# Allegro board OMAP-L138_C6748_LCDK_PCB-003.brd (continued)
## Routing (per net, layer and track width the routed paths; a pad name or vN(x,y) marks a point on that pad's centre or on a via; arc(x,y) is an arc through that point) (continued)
N26585231: length 2.2
  TOP w0.121: v1(11.94,71.63) 12.13,71.82 Q4.1
  BOTTOM w0.121: R28.2 12.19,71.37 v1(11.94,71.63)
N27037804: length 3.2
  TOP w0.121: U9.7 58.4,63.09 58.75,62.74 v1(59.69,62.74)
  BOTTOM w0.121: v1(59.69,62.74) R42.1
N27170750: length 4.6
  TOP w0.121: U3.11 25.9,71.87 25.4,71.37 R19.2 R20.2
N27170752: length 4.4
  TOP w0.121: R18.1 R17.2 24.66,72.37 U3.10
N27473148: length 4.2
  TOP w0.121: v1(22.86,5.84) 22.86,4.12 J11.3
  BOTTOM w0.121: R150.2 C173.2 v1(22.86,5.84)
N27493630: length 14.1
  TOP w0.254: v1(85.09,10.16) 85.02,10.23 U8.16 ; U8.1 80.01,14.52 v1(80.01,15.24)
  LYR3 w0.457: v1(85.09,10.16) v1(80.01,10.16)
  LYR4 w0.457: v1(80.01,15.24) v1(80.01,10.16)
  BOTTOM w0.457: v1(85.09,10.16) C21.1 ; v1(80.01,15.24) C20.1 ; R30.1 v1(80.01,10.16)
N27494415: length 9.3
  TOP w0.254: U8.19 v1(86.09,11.95)
  BOTTOM w0.457: C22.1 FB2.1 87.12,10.92 v1(86.09,11.95) 85.85,12.19 C23.1
N27494781: length 6.8
  TOP w0.457: J3.1 v1(84.13,8.38)
  BOTTOM w0.457: v1(84.13,8.38) 84.84,8.38 85.09,8.13 C24.1 85.6,7.37 85.85,7.11 85.85,6.1 86.04,5.91 FB2.2
N27611173: length 2.8
  TOP w0.121: v1(65.71,19.56) J16.28
  BOTTOM w0.121: R199.1 65.28,19.13 v1(65.71,19.56)
N27611176: length 2.7
  TOP w0.121: J16.27 v1(65.21,13.46)
  BOTTOM w0.121: v1(65.21,13.46) 65.21,14.41 R198.1
N27655467: length 2.8
  TOP w0.121: v1(15.49,8.62) U26.D1
  BOTTOM w0.121: C211.2 16.51,9.65 15.49,8.64 v1(15.49,8.62)
N27655536: length 4.6
  TOP w0.121: U26.D2 14.22,9.14 15.24,9.14 15.49,9.4 v1(15.49,9.65)
  BOTTOM w0.121: v1(15.49,9.65) 15.49,9.91 16.51,10.92 C212.2
N27655572: length 3.6
  TOP w0.121: U26.B2 14.48,5.84 v1(15.49,5.84)
  BOTTOM w0.121: C213.2 v1(15.49,5.84)
N27655608: length 4.2
  TOP w0.121: v1(11.7,4.84) U26.A4
  BOTTOM w0.121: v1(11.7,4.84) 11.43,4.57 C214.2
N27658869: length 3.8
  TOP w0.121: v1(15.49,7.62) U26.C1
  BOTTOM w0.121: v1(15.49,7.62) 16,7.11 R207.1 R203.2
N27689876: length 1.8
  BOTTOM w0.121: J13.12 95.12,73.41 R181.2
N27790142: length 2.1
  TOP w0.121: v1(7.37,89.66) 6.36,89.66 D2.1
  BOTTOM w0.121: R1.2 7.11,89.41 v1(7.37,89.66)
N27790158: length 21.5
  TOP w0.121: U2.3 8.37,75.7 8.13,75.95 8.13,76.45 v1(8.64,76.96)
  LYR3 w0.133: v1(8.64,76.96) 11.3,79.63 11.3,83.69 7.87,87.12 v1(6.35,87.12)
  BOTTOM w0.121: R1.1 v1(6.35,87.12) 7.87,87.12 8.38,87.63 R270.2
N27799298: length 16.9
  TOP w0.254: v1(54.96,36.1) U7.U12
  LYR3 w0.133: v1(54.96,36.1) 54.36,35.5 54.36,31.75 54.61,31.5 54.61,29.32 v1(55.36,28.57)
  BOTTOM w0.121: R33.1 50.04,24.64 51.56,26.16 54.1,26.16 54.97,27.03 54.97,28.18 55.36,28.56 v1(55.36,28.57)
N27851951: length 2.1
  TOP w0.254: U8.11 v1(81.8,9.14)
  BOTTOM w0.457: v1(81.8,9.14) 81.8,10.15 R30.2
N27881562: length 49.2
  TOP w0.095: v1(60.96,57.91) 61.36,57.51 61.36,57.14 61.75,56.76 61.75,54.2 62.38,53.57 62.38,50.05 62.15,49.81 62.15,44.89 U7.J2
  TOP w0.121: C90.1 v1(46.74,83.06)
  LYR3 w0.102: v1(60.96,57.91) 60.5,58.37 60.5,59.44 58.22,61.72 55.88,61.72 52.83,64.77 52.83,71.04 50.09,73.79 50.09,82.17 48.77,83.49 47.17,83.49 v1(46.74,83.06)
N27882349: length 46.4
  TOP w0.095: U7.J1 61.87,45.41 61.87,49.93 62.1,50.16 62.1,53.45 61.47,54.09 61.47,56.64 v1(60.96,57.15)
  TOP w0.121: C91.1 v1(48.01,83.06)
  LYR3 w0.102: v1(48.01,83.06) 48.13,83.19 48.64,83.19 49.78,82.04 49.78,73.66 52.53,70.92 52.53,64.64 55.75,61.42 58.09,61.42 60.2,59.31 60.2,58.24 60.57,57.87 60.57,57.54 v1(60.96,57.15)
N27882474: length 49.1
  TOP w0.095: U7.L2 60.57,44.91 60.57,50.17 59.84,50.9 59.84,56.12 59.57,56.4 59.57,57.05 59.66,57.15 v1(59.69,57.15)
  TOP w0.121: C92.1 v1(45.21,83.06)
  LYR3 w0.102: v1(45.21,83.06) 45.33,83.06 45.38,83.01 45.59,83.01 46.48,82.12 48.18,82.12 48.97,81.33 48.97,73.2 51.51,70.66 51.51,63.37 54.36,60.53 57.58,60.53 58.8,59.31 58.8,58.37 59.3,57.87 59.3,57.54 v1(59.69,57.15)
N27882599: length 50.1
  TOP w0.095: v1(59.69,57.91) 59.29,57.51 59.29,56.28 59.56,56.01 59.56,50.79 60.29,50.06 60.29,45.43 U7.L1
  TOP w0.121: C93.1 v1(43.94,83.06)
  LYR3 w0.102: v1(43.94,83.06) 44.33,83.45 45.58,83.45 46.61,82.42 48.31,82.42 49.28,81.46 49.28,73.33 51.82,70.79 51.82,63.5 54.48,60.83 57.71,60.83 59.11,59.44 59.11,58.5 v1(59.69,57.91)
N28002926: length 2.6
  TOP w0.121: R43.1 v1(60.96,22.1)
  BOTTOM w0.121: Y3.3 60.96,23.09 v1(60.96,22.1)
N28068081: length 2.3
  TOP w0.121: v1(82.3,40.13) D6.2
  BOTTOM w0.121: R210.2 v1(82.3,40.13)
N28068095: length 1.4
  TOP w0.121: D6.1 Q5.6
N28068166: length 1.6
  TOP w0.121: v1(87.12,41.4) 86.6,41.4 D7.2
  BOTTOM w0.121: v1(87.12,41.4) R211.2
N28068180: length 2.6
  TOP w0.121: D7.1 85.85,42.66 85.6,42.41 85.6,41.4 85.36,41.16 Q5.3
N28115819: length 2.3
  TOP w0.121: D5.2 v1(80.01,40.13)
  BOTTOM w0.121: v1(80.01,40.13) R87.1
N28153433: length 8.2
  BOTTOM w0.121: S3.1 98.77,6.13 98.04,6.86 R223.1 97.28,8.12 S3.2
N28153568: length 8.5
  BOTTOM w0.121: S2.2 5.3,18.58 4.57,19.3 R222.1 3.82,20.32 S2.1
N28157154: length 3.2
  TOP w0.121: v1(50.8,62.74) SW1.16
  BOTTOM w0.121: R76.2 v1(50.8,62.74)
N28157182: length 3.2
  TOP w0.121: v1(53.34,62.74) SW1.15
  BOTTOM w0.121: R77.2 v1(53.34,62.74)
N28157237: length 3.2
  TOP w0.121: v1(55.88,62.74) SW1.14
  BOTTOM w0.121: R78.2 v1(55.88,62.74)
N28157266: length 4
  TOP w0.121: SW1.13 58.67,60.58 58.67,58.17 v1(58.42,57.91)
  BOTTOM w0.121: R79.2 v1(58.42,57.91)
N28226673: length 3.2
  TOP w0.121: v1(60.96,62.74) SW1.12
  BOTTOM w0.121: R253.2 v1(60.96,62.74)
N28226728: length 3.2
  TOP w0.121: v1(68.58,62.74) SW1.9
  BOTTOM w0.121: R256.2 v1(68.58,62.74)
N28226757: length 3.2
  TOP w0.121: v1(66.04,62.74) SW1.10
  BOTTOM w0.121: R255.2 v1(66.04,62.74)
N28226786: length 3.2
  TOP w0.121: v1(63.5,62.74) SW1.11
  BOTTOM w0.121: R254.2 v1(63.5,62.74)
N28488580: length 20
  TOP w0.457: TP20.1 17.36,4.66 16.51,3.81 8.89,3.81 8.06,4.64 8.06,7.11 ; v1(6.35,7.11) 8.06,7.11 ; 8.06,7.11 TP19.1
  BOTTOM w0.457: v1(6.35,7.11) R268.2 7.37,6.6 7.45,6.52 D8.2
N28488978: length 2.5
  TOP w0.457: U26.B5 v1(9.92,6.62)
  BOTTOM w0.457: R268.1 9.43,7.11 v1(9.92,6.62)
N28544289: length 27.7
  TOP w0.121: R269.2 78.74,24.89 77.47,23.62 v1(77.47,22.35)
  TOP w0.254: v1(60.56,32.1) U7.K17
  LYR3 w0.121: 61.21,30.1 61.21,31.88 60.99,32.1 v1(60.56,32.1)
  LYR3 w0.133: 61.21,30.1 61.21,28.7 65.79,24.13 68.58,24.13 69.85,22.86 76.96,22.86 v1(77.47,22.35)
N28544350: length 22.1
  TOP w0.121: R272.2 v1(80.01,25.4)
  TOP w0.254: v1(62.16,31.3) U7.J18
  LYR3 w0.121: v1(62.16,31.3) 62.56,30.9 62.56,30.1
  LYR3 w0.133: 62.56,30.1 62.56,30.02 64.64,27.94 70.1,27.94 71.12,26.92 78.49,26.92 v1(80.01,25.4)
N28561453: length 3.4
  TOP w0.121: v1(33.02,20.83) 32.78,21.07 U21.69
  BOTTOM w0.121: R274.2 32.32,19.88 32.64,20.19 32.64,20.45 v1(33.02,20.83)
N28567458: length 5.8
  TOP w0.121: J6.5 83.82,25.4 82.04,27.18 R64.1
N200921000: length 2.3
  TOP w0.121: v1(75.95,40.13) D4.2
  BOTTOM w0.121: R88.1 v1(75.95,40.13)
N281146221: length 1.4
  TOP w0.121: D4.1 Q6.6
N281146431: length 2.6
  TOP w0.121: D5.1 79.5,42.66 79.25,42.41 79.25,41.4 79.01,41.16 Q6.3

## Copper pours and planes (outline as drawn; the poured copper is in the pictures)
1V2_LDO on LYR3: 59.44,30.23 59.18,30.48 59.18,31.24 58.93,31.5 58.67,31.5 58.42,31.75 58.42,33.78 58.93,34.29 58.93,37.85 57.91,38.86 57.91,40.01 58.45,40.13 57.91,40.26 57.91,44.45 57.66,44.7 57.15,44.7 56.9,44.96 56.9,46.48 57.15,46.74 58.67,46.74 58.93,46.48 58.93,46.23 59.18,45.97 59.69,45.97 59.94,45.72 59.94,40.64 60.2,40.39 61.09,40.39 61.72,39.75 63.12,39.75 64.26,38.61 64.26,36.32 61.09,33.15 59.69,33.15 59.56,33.02 59.56,32.13 60.2,31.5 60.2,30.48 59.94,30.23
1V8_LDO on LYR3: 60.2,46.48 60.2,47.75 59.94,48.01 54.61,48.01 54.36,47.75 54.36,39.62 55.75,38.23 56.01,38.23 56.9,37.34 56.9,34.29 57.15,34.04 58.17,34.04 58.67,34.54 58.67,37.59 57.66,38.61 57.66,44.2 57.4,44.45 56.9,44.45 56.64,44.7 56.64,46.74 56.9,46.99 58.93,46.99 59.18,46.74 59.18,46.48 59.44,46.23 59.94,46.23
5V_IN on TOP: 10.29,76.2 11.3,76.2 11.3,77.34 11.94,77.98 13.97,77.98 14.48,78.49 14.48,80.77 13.97,81.28 11.94,81.28 10.29,79.63 10.29,76.88 9.83,76.88 9.83,76.52 10.29,76.52
GND_EARTH on LYR2_GND, LYR5_PWR: 63.75,0.51 63.75,7.37 64.26,7.87 65.28,7.87 65.79,7.37 65.79,4.32 66.55,3.56 76.2,3.56 76.96,4.32 76.96,7.37 77.47,7.87 78.49,7.87 78.99,7.37 78.99,4.32 79.76,3.56 91.69,3.56 91.69,2.29 92.46,1.52 99.31,1.52 100.08,2.29 100.08,88.9 99.31,89.66 54.61,89.66 53.85,88.9 53.85,87.38 53.34,86.87 51.56,86.87 51.05,87.38 51.05,89.15 50.29,89.92 41.66,89.92 40.89,89.15 40.89,88.14 40.39,87.63 34.29,87.63 33.78,88.14 33.78,89.41 33.02,90.17 26.67,90.17 25.91,89.41 25.91,88.14 25.4,87.63 23.37,87.63 22.86,88.14 22.86,90.93 57.91,90.93 58.42,90.42 69.34,90.42 69.85,90.93 101.09,90.93 101.09,0.51
VCC_1V3D on BOTTOM: 42.42,73.15 42.42,74.17 42.67,74.42 43.43,74.42 43.94,74.93 43.94,79.5 43.43,80.01 38.86,80.01 38.86,78.49 38.61,78.23 34.04,78.23 34.04,80.01 34.54,80.52 36.07,80.52 36.83,81.28 44.45,81.28 45.47,80.26 45.47,73.15 47.5,71.12 47.5,61.47 49.02,59.94 49.02,54.86 49.53,54.36 57.53,54.36 60.96,50.93 60.96,47.24 61.72,47.24 61.98,46.99 61.98,45.85 61.72,45.59 61.09,45.59 60.2,46.48 60.2,49.78 57.15,52.83 48.77,52.83 47.5,54.1 47.5,57.66 45.97,59.18 45.97,70.36 43.43,72.9 42.67,72.9
VCC_1V3D on LYR3: 61.21,46.74 61.72,46.74 61.98,46.48 61.98,43.18 62.23,42.93 65.28,42.93 65.53,42.67 65.53,42.29 65.28,42.04 65.15,42.04 64.14,41.02 64.14,40.01 63.88,39.75 63.63,39.75 62.74,40.64 60.45,40.64 60.2,40.89 60.2,41.15 60.71,41.66 60.71,46.23
VCC_1V3D on LYR3: 66.8,29.72 66.55,29.46 65.79,29.46 65.53,29.72 65.53,31.24 64.77,32 64.77,33.78 65.28,34.29 66.29,34.29 66.8,33.78
VCC_1V3D on LYR4: 61.72,46.74 61.98,46.48 61.98,43.18 62.23,42.93 63.75,42.93 64.01,42.67 64.01,37.85 64.26,37.59 64.26,36.83 65.53,35.56 65.53,33.53 62.23,33.53 61.98,33.78 61.98,34.29 60.2,36.07 60.2,37.34 59.69,37.85 58.93,37.85 58.67,38.1 58.67,40.89 58.93,41.15 60.45,41.15 60.71,41.4 60.71,46.48 60.96,46.74
VCC_1V8D on BOTTOM: 8.51,57.4 10.67,57.4 11.18,56.9 11.18,54.61 11.43,54.36 12.45,54.36 12.7,54.61 12.7,56.39 13.21,56.9 28.7,56.9 29.21,56.39 29.21,22.35 29.46,22.1 30.73,22.1 30.99,22.35 30.99,48.51 31.24,48.77 34.04,48.77 34.04,47.5 34.29,47.24 36.2,47.24 36.45,47.5 36.45,48.51 36.7,48.77 38.86,48.77 39.12,48.51 39.12,47.5 39.37,47.24 41.15,47.24 41.4,47.5 41.4,48.77 41.66,49.02 45.97,49.02 46.99,50.04 54.36,50.04 54.74,49.66 54.74,48.01 54.99,47.75 55.75,47.75 56.01,48.01 56.01,49.91 54.86,51.05 34.29,51.05 34.04,50.8 32,50.8 31.75,51.05 31.75,58.17 32.26,58.67 44.96,58.67 45.47,59.18 45.47,70.1 44.2,71.37 36.32,71.37 34.04,69.09 34.04,68.07 38.61,68.07 38.86,68.33 38.86,69.85 43.43,69.85 43.94,69.34 43.94,64.77 41.91,64.77 41.4,64.26 41.4,60.45 41.15,60.2 12.45,60.2 12.45,60.71 12.19,60.96 10.16,60.96 9.65,60.45 9.65,58.67 9.14,58.17 8.51,58.17 7.75,58.93 7.37,58.93 7.37,58.55
VCC_1V8D on LYR4: 56.13,41.15 58.17,41.15 58.42,40.89 58.42,38.1 58.17,37.85 54.61,37.85 52.83,39.62 52.83,49.78 53.09,50.04 55.88,50.04 56.13,49.78 56.13,47.24 55.88,46.99 53.98,46.99 53.59,46.61 53.59,42.55 54.74,41.4 55.88,41.4
VCC_1V8D on LYR4: 30.23,28.7 29.72,28.19 29.72,19.05 30.23,18.54 46.23,18.54 46.74,19.05 46.74,25.15 43.18,28.7
VCC_1V8D on LYR5_PWR: 29.72,48.77 29.97,49.02 42.67,49.02 42.93,48.77 42.93,33.02 48.51,27.43 52.45,27.43 54.48,29.46 54.48,32.51 54.86,32.89 55.24,32.89 55.88,33.53 55.88,34.54 56.13,34.8 56.77,34.8 57.15,35.18 57.15,40.89 57.4,41.15 59.82,41.15 60.2,41.53 60.2,42.67 60.45,42.93 60.96,42.93 61.21,42.67 61.21,42.29 61.59,41.91 63.12,41.91 63.25,41.78 63.25,38.1 64.01,37.34 64.01,35.18 63.88,35.05 61.21,35.05 61.09,35.18 61.09,36.2 60.71,36.58 59.31,36.58 58.42,35.69 58.42,34.54 57.66,33.78 57.66,32.13 57.28,31.75 55.88,31.75 55.37,31.24 55.37,28.32 54.61,27.56 54.61,24.64 54.36,24.38 43.31,24.38 40.51,27.18 30.1,27.18 29.72,27.56
VCC_3V3D on LYR5_PWR: 0.51,0.51 10.67,0.51 10.67,3.05 21.08,3.05 21.08,0.51 63.25,0.51 63.25,7.62 64.01,8.38 65.53,8.38 66.29,7.62 66.29,4.57 66.8,4.06 75.95,4.06 76.45,4.57 76.45,7.62 77.22,8.38 78.74,8.38 79.5,7.62 79.5,4.57 80.01,4.06 92.2,4.06 92.2,2.54 92.71,2.03 99.06,2.03 99.57,2.54 99.57,88.65 99.06,89.15 54.86,89.15 54.36,88.65 54.36,87.12 53.59,86.36 51.31,86.36 50.55,87.12 50.55,88.9 50.04,89.41 41.91,89.41 41.4,88.9 41.4,87.88 40.64,87.12 34.04,87.12 33.27,87.88 33.27,89.15 32.77,89.66 26.92,89.66 26.42,89.15 26.42,87.88 25.65,87.12 23.11,87.12 22.35,87.88 22.35,90.93 0.51,90.93 ; 1 cut-out
VCC_5VD on LYR3: 20.83,81.79 33.53,81.79 35.56,83.82 40.13,83.82 40.64,83.31 40.64,64.01 40.13,63.5 24.64,63.5 23.11,65.02 20.83,65.02 20.32,65.53 20.32,81.28
VCC_AIC3106_1V8D on TOP: 22.61,33.78 22.35,34.04 20.07,34.04 18.54,32.51 18.54,32 18.54,31.94 22.35,31.94 22.61,32.19
VCC_AIC3106_3V3A on TOP: 18.54,24.77 17.02,23.24 17.02,23.11 17.27,22.86 20.32,22.86 20.57,23.11 20.57,25.4 19.42,26.56 18.58,26.56 18.54,26.53
VCC_AIC3106_3V3D on TOP: 13.21,23.11 13.46,22.86 14.48,22.86 14.73,23.11 14.73,24.89 14.61,25.02 14.61,25.78 13.88,25.78 13.88,25.05 13.21,24.38
AUDIO_LEFT on BOTTOM (solid shape): 44.38,7.03 43.61,6.27 42.81,7.07 42.79,7.12 42.81,7.16 43.61,7.8
AUDIO_RIGHT on BOTTOM (solid shape): 35.93,7.16 35.95,7.12 35.93,7.07 35.13,6.27 34.36,7.03 35.13,7.8
CVI_AGND on TOP: 66.55,74.68 66.55,67.56 70.61,67.56 70.61,74.68
CVI_AGND on TOP: 24.64,18.54 28.7,18.54 29.21,19.05 29.21,33.02 28.7,33.53 24.64,33.53 24.13,33.02 24.13,19.05
CVI_AGND on TOP: 53.72,69.09 56.52,69.09 56.52,70.48 57.28,71.25 57.28,75.95 57.02,76.2 53.72,76.2 53.47,75.95 53.47,69.34
CVI_AGND on BOTTOM: 55.12,46.23 54.86,45.97 54.86,44.32 55.63,43.56 55.75,43.56 56.26,43.05 56.77,43.05 57.02,43.31 57.02,46.48 56.77,46.74 56.39,46.74 55.88,46.23
CVI_AGND on LYR2_GND: 0.51,0.51 10.67,0.51 10.67,3.05 21.08,3.05 21.08,0.51 63.25,0.51 63.25,7.62 64.01,8.38 65.53,8.38 66.29,7.62 66.29,4.57 66.8,4.06 75.95,4.06 76.45,4.57 76.45,7.62 77.22,8.38 78.74,8.38 79.5,7.62 79.5,4.57 80.01,4.06 92.2,4.06 92.2,2.54 92.71,2.03 99.06,2.03 99.57,2.54 99.57,88.65 99.06,89.15 54.86,89.15 54.36,88.65 54.36,87.12 53.59,86.36 51.31,86.36 50.55,87.12 50.55,88.9 50.04,89.41 41.91,89.41 41.4,88.9 41.4,87.88 40.64,87.12 34.04,87.12 33.27,87.88 33.27,89.15 32.77,89.66 26.92,89.66 26.42,89.15 26.42,87.88 25.65,87.12 23.11,87.12 22.35,87.88 22.35,90.93 0.51,90.93 ; 1 cut-out
CVI_AGND on LYR5_PWR: 43.18,48.77 43.43,49.02 52.07,49.02 53.72,47.37 53.72,44.7 54.74,43.69 56.64,43.69 56.9,43.43 56.9,35.31 56.64,35.05 56.01,35.05 55.63,34.67 55.63,33.66 55.12,33.15 54.74,33.15 54.23,32.64 54.23,29.59 52.32,27.69 48.64,27.69 43.18,33.15
DDR_VREF on LYR4: 54.1,46.74 54.36,46.74 54.61,46.48 54.61,44.07 54.86,43.81 56.01,43.81 56.9,42.93 56.9,41.66 56.64,41.4 56.26,41.4 55.75,41.91 54.61,41.91 53.85,42.67 53.85,46.48
GPIO2-4 on BOTTOM (solid shape): 3.48,23.12 3.49,23.08 3.48,23.03 2.8,22.36 2.07,23.08 2.8,23.79
GPIO2-4 on BOTTOM (solid shape): 8.59,22.06 7.63,22.06 7.59,22.08 7.57,22.12 7.57,23.08 8.6,23.09
GPIO2-4 on LYR3 (solid shape): 8.54,24.47 8.59,24.49 8.63,24.47 9.3,23.79 8.59,23.06 7.87,23.79
GPIO2-5 on BOTTOM (solid shape): 94.99,8.88 94.31,8.21 94.27,8.19 94.23,8.21 93.55,8.88 94.27,9.62
GPIO2-5 on BOTTOM (solid shape): 95.23,4.11 95.27,4.1 95.29,4.05 95.29,3.1 94.26,3.09 94.27,4.11
GPIO2-5 on LYR3 (solid shape): 95.22,10.62 95.27,10.6 95.29,10.55 95.29,9.6 94.26,9.59 94.27,10.62
RTC_CVDD on LYR4: 59.44,34.8 59.94,34.8 60.2,35.05 60.2,35.69 59.94,35.94 59.94,37.08 59.44,37.59 54.36,37.59 54.1,37.34 54.1,36.58 54.36,36.32 58.42,36.32 59.18,35.56 59.18,35.05
VDCDC1 on TOP: 23.62,76.58 23.37,76.33 23.37,74.3 23.62,74.04 25.53,74.04 26.16,73.41 28.7,73.41 28.83,73.53 28.83,74.17 28.32,74.68 27.43,74.68 27.18,74.93 27.18,76.33 26.92,76.58
VDCDC2 on TOP: 32.77,69.47 32.64,69.34 32.64,67.94 33.78,66.8 33.78,66.29 36.2,63.88 38.61,63.88 38.86,64.14 38.86,66.29 38.61,66.55 35.56,66.55 35.31,66.8 35.31,67.44 33.27,69.47
VDCDC3 on TOP: 33.15,75.69 33.15,74.55 32.89,74.3 32.26,74.3 32.13,74.17 32.13,73.41 35.81,73.41 36.45,74.04 38.61,74.04 38.86,74.3 38.86,76.33 38.61,76.58 34.04,76.58
N17236488 on BOTTOM (solid shape): 34.14,10.61 34.18,10.59 34.2,10.55 34.2,9.53 33.11,9.52 33.12,10.61
N17236492 on BOTTOM (solid shape): 45.62,10.61 45.63,9.52 44.54,9.53 44.54,10.55 44.56,10.59 44.6,10.61
N17548747 on TOP (solid shape): 53.17,80.76 53.19,80.72 53.17,80.68 52.5,80 51.76,80.72 52.5,81.44
N17548747 on BOTTOM (solid shape): 51.74,75.61 51.78,75.63 51.82,75.61 52.5,74.94 51.78,74.2 51.06,74.94
N17548747 on BOTTOM (solid shape): 52.5,80 51.82,79.33 51.78,79.31 51.74,79.33 51.06,80 51.78,80.74
N26107809 on TOP: 23.37,79.76 23.62,80.01 27.18,80.01 29.97,77.22 29.97,75.18 29.72,74.93 29.72,74.3 28,76.01 28,77.03 26.67,78.36 23.62,78.36 23.37,78.61
N26126911 on TOP: 33.53,70.36 34.1,69.79 34.1,69.28 35.31,68.07 38.61,68.07 38.86,68.33 38.86,70.23 38.61,70.48 33.66,70.48
N26141295 on TOP: 31.11,74.55 31.37,74.55 31.62,74.8 31.62,75.31 34.67,78.36 38.61,78.36 38.86,78.61 38.86,79.76 38.61,80.01 33.53,80.01 30.73,77.22 30.73,75.56 31.11,75.18
N26169371 on LYR2_GND: 36.83,73.15 28.7,73.15 28.45,72.9 28.45,69.34 28.7,69.09 32,69.09 33.27,70.36 36.58,70.36 37.08,70.87 37.08,72.9
N28153433 on BOTTOM (solid shape): 98.73,4.49 98.77,4.51 98.81,4.49 99.49,3.82 98.77,3.08 98.05,3.82
N28153433 on BOTTOM (solid shape): 98.77,8.59 97.81,8.59 97.77,8.6 97.75,8.65 97.75,9.6 98.78,9.61
N28153568 on BOTTOM (solid shape): 3.04,19.6 3.08,19.58 3.1,19.54 3.1,18.58 2.07,18.57 2.08,19.6
N28153568 on BOTTOM (solid shape): 8.6,18.58 7.87,17.86 7.19,18.54 7.17,18.58 7.19,18.62 7.87,19.3

Small or netless copper shapes (teardrops, artwork), in the pictures only: 661 on TOP, 390 on BOTTOM, 374 on LYR3, 261 on LYR4

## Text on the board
BOTTOM: 6 | OMAP-L138/C6748 LCDK-PCB-003 | LAYER 6 (BOTTOM SIDE)
Board Geometry/Soldermask Bottom: SMS     (BOTTOM SOLDERMASK)
Ref Des/Silkscreen Bottom: BSLK    (BOTTOM SILKSCREEN)
User.Comments: OMAP-L138/C6748 LCDK-PCB-002 | CIRCUITCO  12/20/2011 | TOP SIDE VIEW | BOTTOM SIDE VIEW
TOP: 1 | LAYER 1 (TOP SIDE)
Board Geometry/Soldermask Top: SMC     (TOP SOLDERMASK)
Ref Des/Silkscreen Top: GND | FINGERPRINT | 3V3 | LINE IN | (TOP) | 1V3 | 1V8 | LINE OUT | (BOT) | USB OTG | CAMERA | USB HOST | UART-USB | MII ENET | LCD | 5VIN | USER 1 | MIC | RESET | USER 2 | TSLK    (TOP SILKSCREEN)
LYR2_GND: 2 | LAYER 2 (GROUND PLANE)
LYR3: 3 | LAYER 3 (INNER SIGNAL)
LYR4: 4 | LAYER 4 (INNER SIGNAL)
LYR5_PWR: 5 | LAYER 5 (POWER PLANE)
BODY_CENTER: SPC     (TOP PASTEMASK)
DISPLAY_TOP: SPS     (BOTTOM PASTEMASK)
DIMENSION: DSP+ARM L13x/C674x Development Kit Rev.
PAGE_OUTLINE: C6000 L13x/C674x Development Kit Rev.
DEVICE_TYPE_BOTTOM: BAR CODE
PLACE_BOUND_TOP: LAYER 1 - PRIMARY SIDE - SIGNAL | LAYER 2 - GROUND PLANE | LAYER 3 - SIGNAL | LAYER 4 - SIGNAL | LAYER 5 - SPLIT POWER PLANE | LAYER 6 - SECONDARY SIDE - SIGNAL | LAYER# | COPPER WEIGHT | HALF+PLATING | (OZ) | 1 | IMPEDANCE CONTROL | +/- 10% | 50ohm SINGLE ENDED | TRACE WIDTH | 5.25 | 4.75 | TRACE WIDTH / SPACE | 90ohm DIFFERENTIAL | 4.5/6.5 | 5.0/7.0 | 100ohm DIFFERENTIAL | 3.75/7.25 | 4.00/8.00 | 10. ALL VIAS TO HAVE SOLDERMASK. | 9. PLATED THROUGH SLOT INDICATED WITH MULTIPLE DRILL HITS SHOULD BE | FINISHED AS SMOOTH WALL BY VEDOR. | PROCESS NOTES: | 2. APPLY LPI SOLDERMASK OVER BARE COPPER (SMOBC), | COLOR: GREEN. SOLDERMASK SHALL | CONFORM TO IPC-SM-840, CLASS H. CURRENT REV. | 3. SOLDERMASK ARTWORK HAS ZERO (0) OVERSIZED PADS. | FABRICATION VENDOR IS ALLOWED TO ADJUST THE COMPONENT | SOLDERMASK PADS TO MEET THEIR TOOLING REQUIREMENTS. | 4. APPLY LPI SILKSCREEN OR EQUIVALENT PER THE ARTWORK. | COLOR: WHITE. | 1. PLATE ALL EXPOSED AREAS WITH ELECTROLESS | IMMERSION GOLD, NICKEL 150 MICROINCHES THK MIN | GOLD 5-15 MICROINCHES THK MIN. | SUPPLIED IPC-D-356 NETLIST. | 4. BOARD MATERIAL & CONSTRUCTION SHOULD MEET OR EXCEED UL | FLAMMABILITY RATING 94V-0 AND IT SHOULD BE MARKED ON BOARD. | FAB NOTES: | 1. ALL DIMENSIONS ARE IN INCHES, UNLESS | OTHERWISE NOTED. | 2. THE PWB SHALL BE FABRICATED TO IPC-6012, | CLASS 2 AND WORKMANSHIP SHALL CONFORM TO | IPC-A-600, CLASS 2. CURRENT REVISIONS. | 3. BOARD MATERIAL SHALL BE 180 Tg/350 Td ISOLA FR-370HR | OR EQUIVALENT, RoHS COMPLIANT AND LEAD FREE | ASSEMBLY CAPABLE.  BOARD MATERIAL SHALL | MEET OR EXCEED IPC-4101B. COLOR: NATURAL. | 5. MINIMUM COPPER WALL THICKNESS OF PLATED-THRU | HOLES TO BE .001 INCH, WITH A MINIMUM | ANNULAR RING OF .002 INCH. | 6. OVERALL BOARD THICKNESS TO BE .062 +/- 10% | AND APPLIES AFTER ALL LAMINATION AND PLATING | PROCESSES, MEASURED FROM COPPER TO COPPER. | 7. MAX. WARP & TWIST TO BE .0075 INCHES PER INCH. | 8. BOARD MUST BE ELECTRICALLY TESTED USING | LAYER STACK-UP - ALL DIMENSIONS IN INCHES
User.12: FIGURE | SIZE | 8.0 | 12.0 | 28.0 | 30.0 | 35.0 | 40.0 | 42.0 | 45.0 | 55.0 | 59.0 | 62.0 | 71.0 | 76.0 | 120.0 | 140.0 | 156.0 | 67.0 | 77.0 | 128.0 | 95.0x40.0 | 86.61x78.74 | DRILL CHART: TOP to BOTTOM | ALL UNITS ARE IN MILS | TOLERANCE | +3.0/-3.0 | +5.0/-5.0 | PLATED | NON-PLATED | QTY | 1275 | 100 | 55 | 7 | 8 | 139 | 12 | 2 | 6 | 1 | 4
